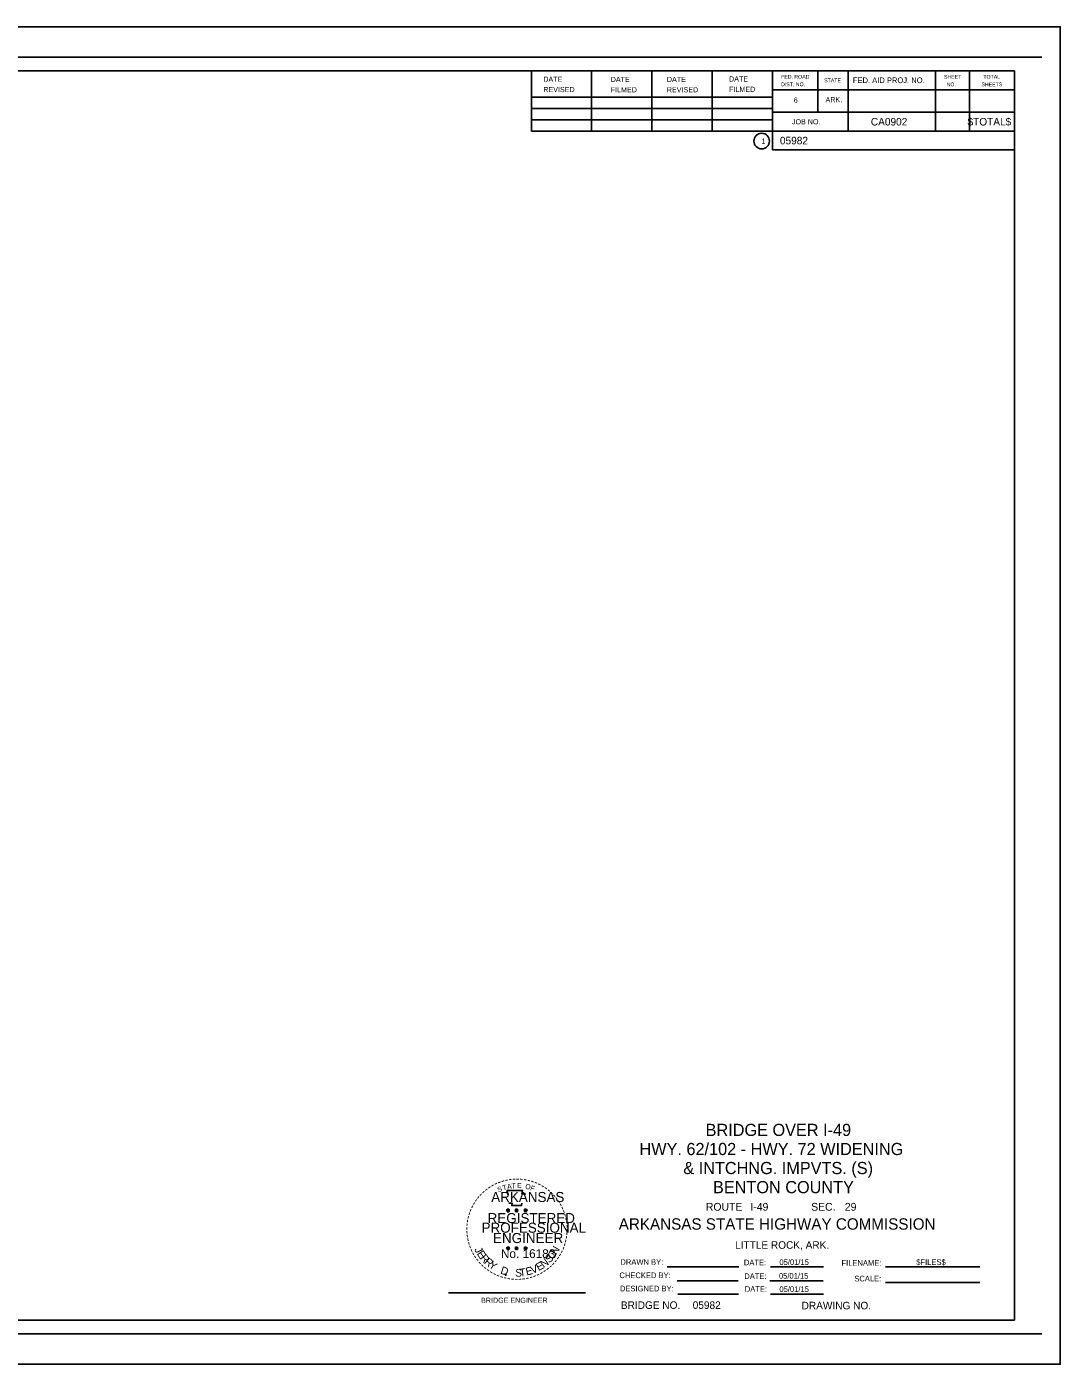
# Model space of a CAD drawing. Extents: x -30250 to -30216, y 5204 to 5226.
# Drawn here: x -30233 to -30216, y 5203.98 to 5225.98 of the extents above; entities that cross this region are included whole.
import ezdxf

# ---------------------------------------------------------------- set-up
doc = ezdxf.new("R2010")
doc.units = 0
for name, color, linetype in [('1', 7, 'Continuous'), ('B_Sheet Number', 7, 'Continuous'), ('B_Title Block Layout', 7, 'Continuous'), ('No Plot Border', 7, 'Continuous')]:
    doc.layers.add(name, color=color, linetype=linetype)

msp = doc.modelspace()

# ---------------------------------------------------------------- linework, layer by layer
at = {"layer": '1'}
for p, q in [((-30248.364, 5225.255), (-30216.746, 5225.255)), ((-30224.694, 5225.255), (-30224.694, 5224.264)), ((-30223.704, 5224.264), (-30223.704, 5225.255)), ((-30222.714, 5224.264), (-30222.714, 5225.255)), ((-30221.719, 5224.264), (-30221.719, 5225.255)), ((-30220.728, 5223.954), (-30220.728, 5225.255)), ((-30219.984, 5224.575), (-30219.984, 5225.255)), ((-30219.487, 5224.264), (-30219.487, 5225.255)), ((-30218.046, 5225.255), (-30218.046, 5224.264)), ((-30217.49, 5225.255), (-30217.49, 5224.264)), ((-30216.746, 5204.711), (-30216.746, 5225.255)), ((-30220.732, 5224.821), (-30224.694, 5224.821)), ((-30216.746, 5224.944), (-30220.728, 5224.944)), ((-30220.728, 5224.634), (-30224.694, 5224.634)), ((-30216.746, 5224.575), (-30220.728, 5224.575)), ((-30220.728, 5224.451), (-30224.694, 5224.451)), ((-30216.746, 5224.264), (-30224.694, 5224.264)), ((-30216.746, 5223.954), (-30220.728, 5223.954)), ((-30225.108, 5206.522), (-30225.06, 5206.487)), ((-30225.108, 5206.522), (-30225.049, 5206.522)), ((-30225.078, 5206.543), (-30225.096, 5206.487)), ((-30225.049, 5206.522), (-30225.096, 5206.487)), ((-30225.078, 5206.543), (-30225.06, 5206.487)), ((-30224.97, 5206.522), (-30224.922, 5206.487)), ((-30224.97, 5206.522), (-30224.91, 5206.522)), ((-30224.94, 5206.543), (-30224.958, 5206.487)), ((-30224.91, 5206.522), (-30224.958, 5206.487)), ((-30224.94, 5206.543), (-30224.922, 5206.487)), ((-30224.82, 5206.522), (-30224.773, 5206.487)), ((-30224.82, 5206.522), (-30224.761, 5206.522)), ((-30224.79, 5206.543), (-30224.809, 5206.487)), ((-30224.761, 5206.522), (-30224.809, 5206.487)), ((-30224.79, 5206.543), (-30224.773, 5206.487)), ((-30225.108, 5205.898), (-30225.06, 5205.863)), ((-30225.108, 5205.898), (-30225.049, 5205.898)), ((-30225.078, 5205.919), (-30225.096, 5205.863)), ((-30225.049, 5205.898), (-30225.096, 5205.863)), ((-30225.078, 5205.919), (-30225.06, 5205.863)), ((-30224.97, 5205.898), (-30224.922, 5205.863)), ((-30224.97, 5205.898), (-30224.91, 5205.898)), ((-30224.94, 5205.919), (-30224.958, 5205.863)), ((-30224.91, 5205.898), (-30224.958, 5205.863)), ((-30224.94, 5205.919), (-30224.922, 5205.863)), ((-30224.82, 5205.898), (-30224.773, 5205.863)), ((-30224.82, 5205.898), (-30224.761, 5205.898)), ((-30224.79, 5205.919), (-30224.809, 5205.863)), ((-30224.761, 5205.898), (-30224.809, 5205.863)), ((-30224.79, 5205.919), (-30224.773, 5205.863)), ((-30222.461, 5205.584), (-30221.285, 5205.584)), ((-30220.763, 5205.584), (-30219.888, 5205.584)), ((-30218.869, 5205.584), (-30217.317, 5205.584)), ((-30222.295, 5205.358), (-30221.295, 5205.358)), ((-30220.771, 5205.358), (-30219.896, 5205.358)), ((-30218.869, 5205.327), (-30217.317, 5205.327)), ((-30226.057, 5205.158), (-30223.807, 5205.158)), ((-30222.288, 5205.139), (-30221.288, 5205.139)), ((-30220.763, 5205.139), (-30219.888, 5205.139)), ((-30216.746, 5204.711), (-30248.364, 5204.711))]:
    msp.add_line(p, q, dxfattribs=at)
for points in [[(-30225.098, 5206.841), (-30225.078, 5206.772)], [(-30224.81, 5206.762), (-30224.8, 5206.792), (-30224.85, 5206.782), (-30224.84, 5206.841), (-30225.098, 5206.841)], [(-30225.059, 5206.642), (-30225.059, 5206.632), (-30225.009, 5206.632), (-30225.019, 5206.593), (-30224.86, 5206.593), (-30224.85, 5206.632)]]:
    msp.add_lwpolyline(points, dxfattribs=at)
msp.add_circle((-30225.118, 5205.454), 0.00786, dxfattribs=at)
for centre, radius, start, end in [((-30225.119, 5205.455), 0.00755, 249.7224, 57.042), ((-30225.121, 5205.456), 0.0081, 265.5485, 41.2158)]:
    msp.add_arc(centre, radius, start, end, dxfattribs=at)
msp.add_ellipse((-30220.907, 5224.101), major_axis=(0.128, 0), ratio=0.999873, dxfattribs=at)
at = {"layer": 'No Plot Border'}
for p, q in [((-30216.297, 5225.482), (-30249.497, 5225.482)), ((-30249.497, 5204.485), (-30216.297, 5204.485))]:
    msp.add_line(p, q, dxfattribs=at)
msp.add_lwpolyline([(-30249.996, 5225.981), (-30215.996, 5225.981), (-30215.996, 5203.984), (-30249.996, 5203.984)], close=True, dxfattribs=at)

# ---------------------------------------------------------------- texts
at = {"layer": '1'}
for s, height, p in [('DATE', 0.085, (-30224.499, 5225.076)), ('DATE', 0.085, (-30223.39, 5225.072)), ('DATE', 0.085, (-30222.467, 5225.072)), ('DATE', 0.085, (-30221.443, 5225.08)), ('FED. ROAD', 0.062, (-30220.588, 5225.127)), ('DIST. NO.', 0.062, (-30220.588, 5225.003)), ('STATE', 0.062, (-30219.879, 5225.068)), ('FED. AID PROJ. NO.', 0.093, (-30219.407, 5225.054)), ('SHEET', 0.062, (-30217.908, 5225.126)), (' NO.', 0.062, (-30217.889, 5225.002)), ('SHEETS', 0.062, (-30217.292, 5225.002)), ('TOTAL', 0.062, (-30217.261, 5225.126)), ('REVISED', 0.085, (-30224.499, 5224.906)), ('FILMED', 0.085, (-30223.39, 5224.902)), ('REVISED', 0.085, (-30222.467, 5224.902)), ('FILMED', 0.085, (-30221.443, 5224.91)), ('6', 0.085, (-30220.38, 5224.732)), ('ARK.', 0.085, (-30219.857, 5224.74)), ('JOB NO.', 0.085, (-30220.409, 5224.376)), ('CA0902', 0.124, (-30219.111, 5224.357)), ('1', 0.085, (-30220.91, 5224.059)), ('05982', 0.124, (-30220.607, 5224.047)), ('-', 0.132, (-30224.95, 5206.977)), ('ARKANSAS', 0.1652, (-30225.356, 5206.652)), ('ROUTE', 0.128, (-30221.825, 5206.509)), ('I-49', 0.128, (-30221.092, 5206.509)), ('SEC.', 0.128, (-30220.093, 5206.509)), ('29', 0.128, (-30219.539, 5206.509)), ('PROFESSIONAL', 0.16524, (-30225.515, 5206.147)), ('REGISTERED', 0.1652, (-30225.415, 5206.305)), ('ARKANSAS STATE HIGHWAY COMMISSION', 0.187, (-30223.258, 5206.197)), ('ENGINEER', 0.1652, (-30225.326, 5205.977)), ('No. 16183', 0.145, (-30225.196, 5205.73)), ('LITTLE ROCK, ARK.', 0.124, (-30221.345, 5205.883)), ('DRAWN BY:', 0.093, (-30223.231, 5205.619)), ('DATE:', 0.093, (-30221.2, 5205.612)), ('05/01/15', 0.093, (-30220.615, 5205.617)), ('FILENAME:', 0.093, (-30219.594, 5205.603)), ('$FILES$', 0.093, (-30218.364, 5205.617)), ('CHECKED BY:', 0.093, (-30223.247, 5205.4)), ('DATE:', 0.093, (-30221.193, 5205.386)), ('05/01/15', 0.093, (-30220.623, 5205.391)), ('SCALE:', 0.093, (-30219.383, 5205.346)), ('DESIGNED BY:', 0.093, (-30223.239, 5205.182)), ('DATE:', 0.093, (-30221.185, 5205.175)), ('05/01/15', 0.093, (-30220.615, 5205.172)), ('BRIDGE ENGINEER', 0.08499, (-30225.523, 5204.994)), ('BRIDGE NO.', 0.124, (-30223.223, 5204.894)), ('05982', 0.124, (-30222.042, 5204.894)), ('DRAWING NO.', 0.124, (-30220.25, 5204.887))]:
    msp.add_text(s, height=height, dxfattribs=at).set_placement(p)
for s, height, rotation, p in [('-', 0.132, 25.7142, (-30225.284, 5206.893)), ('-', 0.132, 21.4285, (-30225.231, 5206.917)), ('-', 0.132, 17.1428, (-30225.177, 5206.938)), ('-', 0.132, 12.8571, (-30225.121, 5206.954)), ('-', 0.132, 8.5714, (-30225.065, 5206.967)), ('-', 0.132, 4.2857, (-30225.007, 5206.974)), ('E', 0.0826, 0.8323, (-30224.93, 5206.881)), ('-', 0.132, 355.7131, (-30224.892, 5206.977)), ('-', 0.132, 351.4274, (-30224.834, 5206.972)), ('-', 0.132, 347.1417, (-30224.777, 5206.962)), ('-', 0.132, 342.856, (-30224.721, 5206.948)), ('-', 0.132, 338.5703, (-30224.665, 5206.931)), ('-', 0.132, 51.4284, (-30225.548, 5206.672)), ('-', 0.132, 47.1427, (-30225.511, 5206.717)), ('-', 0.132, 42.857, (-30225.471, 5206.759)), ('-', 0.132, 38.5713, (-30225.428, 5206.797)), ('-', 0.132, 34.2856, (-30225.382, 5206.833)), ('-', 0.132, 29.9999, (-30225.334, 5206.865)), ('S', 0.0825, 21.594, (-30225.237, 5206.811)), ('T', 0.0825, 16.4036, (-30225.158, 5206.841)), ('A', 0.0826, 11.2132, (-30225.088, 5206.861)), ('T', 0.0826, 6.0228, (-30225.019, 5206.871)), ('O', 0.0825, 350.4515, (-30224.8, 5206.871)), ('F', 0.0825, 340.0707, (-30224.721, 5206.851)), ('-', 0.132, 334.2846, (-30224.612, 5206.908)), ('-', 0.132, 329.9989, (-30224.56, 5206.882)), ('-', 0.132, 325.7132, (-30224.511, 5206.853)), ('-', 0.132, 321.4275, (-30224.464, 5206.82)), ('-', 0.132, 317.1418, (-30224.419, 5206.783)), ('-', 0.132, 312.8561, (-30224.377, 5206.743)), ('-', 0.132, 68.5712, (-30225.659, 5206.47)), ('-', 0.132, 64.2855, (-30225.636, 5206.524)), ('-', 0.132, 59.9998, (-30225.61, 5206.576)), ('-', 0.132, 55.7141, (-30225.581, 5206.625)), ('-', 0.132, 308.5704, (-30224.339, 5206.7)), ('-', 0.132, 304.2847, (-30224.303, 5206.654)), ('-', 0.132, 299.999, (-30224.271, 5206.606)), ('-', 0.132, 295.7133, (-30224.243, 5206.556)), ('-', 0.132, 81.4283, (-30225.7, 5206.302)), ('-', 0.132, 77.1426, (-30225.69, 5206.359)), ('-', 0.132, 72.8569, (-30225.676, 5206.415)), ('-', 0.132, 291.4276, (-30224.219, 5206.503)), ('-', 0.132, 287.1419, (-30224.198, 5206.449)), ('-', 0.132, 282.8562, (-30224.182, 5206.393)), ('-', 0.132, 278.5705, (-30224.17, 5206.337)), ('-', 0.132, 89.9997, (-30225.705, 5206.187)), ('-', 0.132, 94.2854, (-30225.702, 5206.129)), ('-', 0.132, 85.714, (-30225.705, 5206.244)), ('-', 0.132, 98.5711, (-30225.695, 5206.072)), ('-', 0.132, 261.4277, (-30224.165, 5206.106)), ('-', 0.132, 265.7134, (-30224.16, 5206.164)), ('-', 0.132, 274.2848, (-30224.162, 5206.279)), ('-', 0.132, 269.9991, (-30224.159, 5206.222)), ('-', 0.132, 102.8568, (-30225.682, 5206.015)), ('-', 0.132, 107.1425, (-30225.666, 5205.959)), ('-', 0.132, 111.4282, (-30225.645, 5205.905)), ('-', 0.132, 115.7139, (-30225.621, 5205.852)), ('J', 0.127, 296.7753, (-30225.637, 5205.874)), ('E', 0.127, 303.4983, (-30225.599, 5205.803)), ('N', 0.127, 59.0798, (-30224.284, 5205.774)), ('-', 0.132, 248.5706, (-30224.205, 5205.937)), ('-', 0.132, 252.8563, (-30224.188, 5205.993)), ('-', 0.132, 257.142, (-30224.175, 5206.049)), ('-', 0.132, 119.9996, (-30225.593, 5205.802)), ('-', 0.132, 124.2853, (-30225.561, 5205.754)), ('-', 0.132, 128.571, (-30225.525, 5205.708)), ('-', 0.132, 132.8567, (-30225.487, 5205.665)), ('R', 0.127, 309.0275, (-30225.547, 5205.728)), ('R', 0.127, 318.2612, (-30225.481, 5205.653)), ('Y', 0.127, 325.5438, (-30225.407, 5205.588)), ('E', 0.127, 29.1612, (-30224.576, 5205.514)), ('N', 0.127, 37.0638, (-30224.493, 5205.563)), ('S', 0.127, 44.4887, (-30224.399, 5205.64)), ('O', 0.127, 51.0136, (-30224.346, 5205.695)), ('-', 0.132, 227.1421, (-30224.353, 5205.691)), ('-', 0.132, 231.4278, (-30224.316, 5205.736)), ('-', 0.132, 235.7135, (-30224.283, 5205.783)), ('-', 0.132, 239.9992, (-30224.254, 5205.832)), ('-', 0.132, 244.2849, (-30224.228, 5205.884)), ('-', 0.132, 137.1424, (-30225.445, 5205.625)), ('-', 0.132, 141.4281, (-30225.4, 5205.588)), ('-', 0.132, 145.7138, (-30225.353, 5205.555)), ('-', 0.132, 149.9995, (-30225.304, 5205.526)), ('-', 0.132, 154.2852, (-30225.252, 5205.5)), ('-', 0.132, 158.5709, (-30225.198, 5205.477)), ('-', 0.132, 162.8566, (-30225.143, 5205.46)), ('D', 0.127, 342.2913, (-30225.213, 5205.477)), ('S', 0.127, 357.358, (-30224.964, 5205.427)), ('T', 0.127, 6.7542, (-30224.884, 5205.426)), ('E', 0.127, 14.4797, (-30224.772, 5205.442)), ('V', 0.127, 21.2613, (-30224.681, 5205.468)), ('-', 0.132, 197.1422, (-30224.687, 5205.47)), ('-', 0.132, 201.4279, (-30224.633, 5205.491)), ('-', 0.132, 205.7136, (-30224.58, 5205.515)), ('-', 0.132, 209.9993, (-30224.53, 5205.543)), ('-', 0.132, 214.285, (-30224.482, 5205.575)), ('-', 0.132, 218.5707, (-30224.436, 5205.611)), ('-', 0.132, 222.8564, (-30224.393, 5205.649)), ('-', 0.132, 167.1423, (-30225.087, 5205.447)), ('-', 0.132, 171.428, (-30225.03, 5205.437)), ('-', 0.132, 175.7137, (-30224.972, 5205.432)), ('-', 0.132, 179.9994, (-30224.915, 5205.431)), ('-', 0.132, 184.2851, (-30224.857, 5205.434)), ('-', 0.132, 188.5708, (-30224.8, 5205.442)), ('-', 0.132, 192.8565, (-30224.743, 5205.454))]:
    msp.add_text(s, height=height, rotation=rotation, dxfattribs=at).set_placement(p)
at = {"layer": 'B_Sheet Number'}
msp.add_text('$TOTAL$', height=0.124, dxfattribs=at).set_placement((-30217.521, 5224.357))
at = {"layer": 'B_Title Block Layout'}
for s, p in [('BRIDGE OVER I-49', (-30221.829, 5207.738)), ('HWY. 62/102 - HWY. 72 WIDENING', (-30222.917, 5207.424)), ('& INTCHNG. IMPVTS. (S)', (-30222.196, 5207.111)), ('BENTON COUNTY', (-30221.708, 5206.797))]:
    msp.add_text(s, height=0.2, dxfattribs=at).set_placement(p)

doc.saveas('drawing.dxf')
